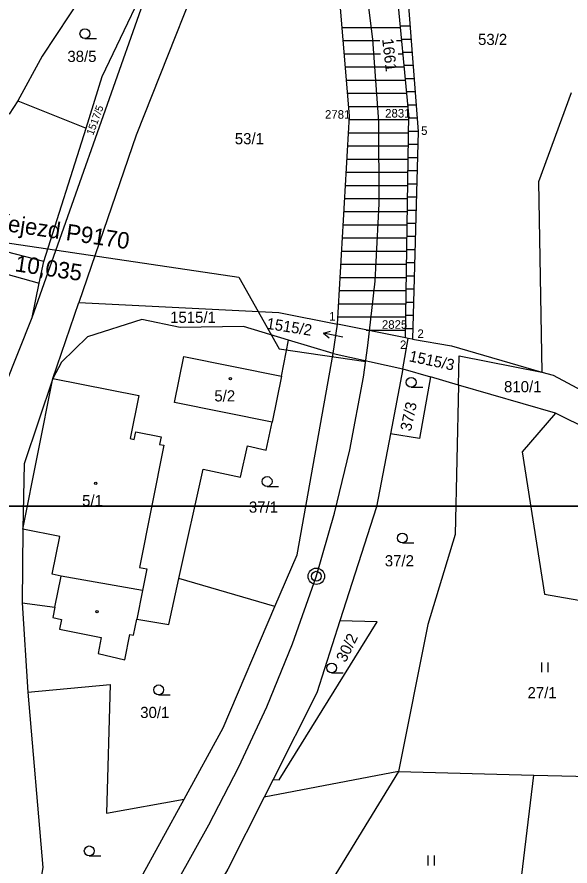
# Model space of a CAD drawing. Extents: x -553916 to -552953, y -1067469 to -1066637.
# Drawn here: x -553557.7 to -553473.7, y -1067154.7 to -1067025.6 of the extents above; entities that cross this region are included whole.
import ezdxf

# ---------------------------------------------------------------- set-up
doc = ezdxf.new("R2010")
doc.units = 0
for name, color, linetype in [('Hranice parcel', 7, 'Continuous'), ('Kolej', 7, 'Continuous'), ('Návěst místo trati', 7, 'Continuous'), ('Parcelní čísla', 7, 'Continuous'), ('Pop  PČ popisy', 7, 'Continuous'), ('Propustek', 7, 'Continuous'), ('Přejezd - štěrkové lože', 7, 'Continuous'), ('Vnitřní kresba', 7, 'Continuous'), ('Vrstva 1', 7, 'Continuous'), ('Vrstva 60', 7, 'Continuous'), ('Značky budov', 7, 'Continuous'), ('Značky kultur', 7, 'Continuous')]:
    doc.layers.add(name, color=color, linetype=linetype)

msp = doc.modelspace()

# ---------------------------------------------------------------- linework, layer by layer
at = {"layer": 'Hranice parcel'}
for p, q in [((-553555.44, -1067071.33), (-553535.85, -1067015.85)), ((-553473.53, -1067037.17), (-553478.45, -1067050.68)), ((-553473.53, -1067037.17), (-553478.45, -1067050.68)), ((-553557.59, -1067038.38), (-553547.23, -1067042.51)), ((-553553.65, -1067062.79), (-553547.23, -1067042.51)), ((-553478.45, -1067050.68), (-553477.96, -1067079.63)), ((-553478.45, -1067050.68), (-553477.96, -1067079.63)), ((-553553.65, -1067062.79), (-553569.79, -1067058.6)), ((-553570.64, -1067061.48), (-553554.35, -1067066.11)), ((-553554.35, -1067066.11), (-553553.65, -1067062.79)), ((-553555.44, -1067071.33), (-553554.35, -1067066.11)), ((-553552.27, -1067080.57), (-553548.33, -1067069.03)), ((-553559.6, -1067081.76), (-553555.44, -1067071.33)), ((-553517.54, -1067080.21), (-553516.45, -1067074.75)), ((-553509.66, -1067076.78), (-553516.45, -1067074.75)), ((-553490.63, -1067081.59), (-553490.53, -1067077.13)), ((-553490.63, -1067081.59), (-553490.53, -1067077.13)), ((-553490.53, -1067077.13), (-553477.96, -1067079.63)), ((-553490.53, -1067077.13), (-553477.96, -1067079.63)), ((-553517.54, -1067080.21), (-553518.94, -1067087.24)), ((-553490.63, -1067081.59), (-553494.87, -1067080.36)), ((-553475.9, -1067085.87), (-553490.63, -1067081.59)), ((-553461.02, -1067093.19), (-553475.9, -1067085.87)), ((-553518.53, -1067115.26), (-553533.13, -1067110.99)), ((-553556.94, -1067114.69), (-553556.09, -1067128.27)), ((-553499.73, -1067140.34), (-553520.16, -1067144.23)), ((-553499.73, -1067140.34), (-553516.39, -1067167.53)), ((-553499.73, -1067140.34), (-553516.39, -1067167.53)), ((-553499.73, -1067140.34), (-553479.18, -1067140.92)), ((-553482.63, -1067169.28), (-553479.18, -1067140.92)), ((-553479.18, -1067140.92), (-553459.64, -1067141.29))]:
    msp.add_line(p, q, dxfattribs=at)
for points in [[(-553515.43, -1066991.08), (-553526.38, -1067010.19), (-553539.65, -1067043.59), (-553548.33, -1067069.03)], [(-553547.23, -1067042.51), (-553544.77, -1067034.69), (-553535.85, -1067015.85)], [(-553547.68, -1067022.12), (-553553.91, -1067031.58), (-553557.59, -1067038.38)], [(-553557.59, -1067038.38), (-553558.91, -1067040.42), (-553564.16, -1067035.68)], [(-553548.33, -1067069.03), (-553517.95, -1067070.55), (-553509.03, -1067072.35)], [(-553516.45, -1067074.75), (-553523.31, -1067072.7), (-553532.92, -1067072.84), (-553538.78, -1067071.62), (-553547.04, -1067074.23), (-553550.96, -1067078.08), (-553552.27, -1067080.57)], [(-553497.61, -1067074.62), (-553491.7, -1067075.64), (-553477.96, -1067079.63)], [(-553518.94, -1067087.24), (-553533.8, -1067084.25), (-553532.39, -1067077.24), (-553517.54, -1067080.21)], [(-553477.96, -1067079.63), (-553476.25, -1067080.06), (-553464.58, -1067086.32)], [(-553552.27, -1067080.57), (-553556.64, -1067093.58), (-553556.86, -1067103.5), (-553556.94, -1067114.69)], [(-553490.63, -1067081.59), (-553491.15, -1067104.31), (-553495.3, -1067118.01), (-553499.73, -1067140.34)], [(-553490.63, -1067081.59), (-553491.15, -1067104.31), (-553495.3, -1067118.01), (-553499.73, -1067140.34)], [(-553475.9, -1067085.87), (-553480.97, -1067091.73), (-553477.55, -1067113.39), (-553465.08, -1067115.55)], [(-553533.13, -1067110.99), (-553529.45, -1067094.35), (-553523.77, -1067095.61), (-553522.71, -1067090.83), (-553519.87, -1067091.46), (-553518.94, -1067087.24)], [(-553540.05, -1067119.63), (-553539.55, -1067117.17), (-553534.67, -1067117.97), (-553533.13, -1067110.99)], [(-553556.94, -1067114.69), (-553551.99, -1067115.38), (-553552.31, -1067116.95)], [(-553552.31, -1067116.95), (-553550.99, -1067117.22), (-553551.28, -1067118.69), (-553544.93, -1067119.96), (-553545.42, -1067122.41), (-553541.36, -1067123.37), (-553540.59, -1067119.53), (-553540.05, -1067119.63)], [(-553518.82, -1067141.56), (-553517.91, -1067141.59), (-553503, -1067117.58), (-553508.67, -1067117.46)], [(-553556.09, -1067128.27), (-553543.56, -1067127.12), (-553544.12, -1067146.66), (-553532.35, -1067144.53)], [(-553556.09, -1067128.27), (-553553.82, -1067154.93), (-553557.64, -1067176.88)]]:
    msp.add_lwpolyline(points, dxfattribs=at)
at = {"layer": 'Kolej'}
for points in [[(-553503.32, -1067065.81), (-553502.68, -1067054.03), (-553502.76, -1067041.5), (-553503.63, -1067029.06), (-553504.76, -1067019.97), (-553506.18, -1067011.39), (-553508.33, -1067001.39), (-553510.95, -1066991.62), (-553512.92, -1066985.29), (-553515.65, -1066977.35), (-553517.42, -1066972.53), (-553519.16, -1066967.95), (-553522.89, -1066958.38), (-553529.1, -1066942.55), (-553538.69, -1066918.11), (-553542.91, -1066907.33), (-553546.69, -1066897.68), (-553555.03, -1066876.44), (-553564.64, -1066851.89), (-553574.24, -1066827.43), (-553583.19, -1066804.62)], [(-553543.17, -1067173.82), (-553538.26, -1067165.53), (-553533.28, -1067156.93), (-553528.57, -1067148.43), (-553524.02, -1067139.63), (-553519.75, -1067130.49), (-553515.84, -1067120.93), (-553512.27, -1067110.73), (-553509.46, -1067101.06), (-553507.13, -1067091.41), (-553505.08, -1067080.38), (-553504.39, -1067075.58), (-553503.32, -1067065.81)]]:
    msp.add_lwpolyline(points, dxfattribs=at)
at = {"layer": 'Návěst místo trati'}
for radius in [1.25, 0.752]:
    msp.add_circle((-553512.25, -1067110.66), radius, dxfattribs=at)
at = {"layer": 'Pop  PČ popisy'}
for p, q in [((-553511.16, -1067073.68), (-553510.07, -1067073.4)), ((-553508.22, -1067074.31), (-553511.16, -1067073.68)), ((-553511.16, -1067073.68), (-553510.28, -1067074.38))]:
    msp.add_line(p, q, dxfattribs=at)
at = {"layer": 'Propustek'}
for p, q in [((-553499.28, -1067010.65), (-553496.78, -1067043.02)), ((-553499.48, -1067026.97), (-553498.02, -1067026.97)), ((-553508.33, -1067027.22), (-553499.45, -1067027.22)), ((-553508.16, -1067029.22), (-553502.6, -1067029.22)), ((-553500.05, -1067029.22), (-553499.26, -1067029.22)), ((-553499.28, -1067028.97), (-553497.87, -1067028.97)), ((-553499.09, -1067030.97), (-553497.71, -1067030.97)), ((-553508, -1067031.22), (-553502.47, -1067031.22)), ((-553499.81, -1067031.22), (-553499.06, -1067031.22)), ((-553507.83, -1067033.22), (-553498.87, -1067033.22)), ((-553498.89, -1067032.97), (-553497.56, -1067032.97)), ((-553507.67, -1067035.22), (-553498.67, -1067035.22)), ((-553498.7, -1067034.97), (-553497.4, -1067034.97)), ((-553507.51, -1067037.22), (-553498.48, -1067037.22)), ((-553498.51, -1067036.97), (-553497.25, -1067036.97)), ((-553507.34, -1067039.22), (-553498.29, -1067039.22)), ((-553498.31, -1067038.97), (-553497.09, -1067038.97)), ((-553507.25, -1067041.22), (-553498.18, -1067041.22)), ((-553498.18, -1067040.97), (-553496.94, -1067040.97)), ((-553507.37, -1067043.22), (-553498.21, -1067043.22)), ((-553498.21, -1067042.97), (-553496.78, -1067042.97)), ((-553496.78, -1067043.02), (-553497.61, -1067074.62)), ((-553498.24, -1067044.97), (-553496.83, -1067044.97)), ((-553507.48, -1067045.22), (-553498.24, -1067045.22)), ((-553507.59, -1067047.22), (-553498.27, -1067047.22)), ((-553498.27, -1067046.97), (-553496.88, -1067046.97)), ((-553498.3, -1067048.97), (-553496.94, -1067048.97)), ((-553507.71, -1067049.22), (-553498.3, -1067049.22)), ((-553507.82, -1067051.22), (-553498.33, -1067051.22)), ((-553498.33, -1067050.97), (-553496.99, -1067050.97)), ((-553507.94, -1067053.22), (-553498.36, -1067053.22)), ((-553498.36, -1067052.97), (-553497.04, -1067052.97)), ((-553508.05, -1067055.22), (-553498.39, -1067055.22)), ((-553498.39, -1067054.97), (-553497.09, -1067054.97)), ((-553508.17, -1067057.22), (-553498.42, -1067057.22)), ((-553498.42, -1067056.97), (-553497.15, -1067056.97)), ((-553508.28, -1067059.22), (-553498.45, -1067059.22)), ((-553498.45, -1067058.97), (-553497.2, -1067058.97)), ((-553508.39, -1067061.22), (-553498.48, -1067061.22)), ((-553498.48, -1067060.97), (-553497.25, -1067060.97)), ((-553508.51, -1067063.22), (-553498.51, -1067063.22)), ((-553498.51, -1067062.97), (-553497.3, -1067062.97)), ((-553508.62, -1067065.22), (-553498.54, -1067065.22)), ((-553498.54, -1067064.97), (-553497.36, -1067064.97)), ((-553498.57, -1067066.97), (-553497.41, -1067066.97)), ((-553508.74, -1067067.22), (-553498.57, -1067067.22)), ((-553508.85, -1067069.22), (-553498.6, -1067069.22)), ((-553498.6, -1067068.97), (-553497.46, -1067068.97)), ((-553498.63, -1067070.97), (-553497.51, -1067070.97)), ((-553508.97, -1067071.22), (-553498.63, -1067071.22)), ((-553498.68, -1067074.42), (-553509.03, -1067072.35)), ((-553504.67, -1067073.22), (-553498.66, -1067073.22)), ((-553498.66, -1067072.97), (-553497.57, -1067072.97)), ((-553498.28, -1067074.5), (-553498.68, -1067074.42)), ((-553497.61, -1067074.62), (-553498.28, -1067074.5))]:
    msp.add_line(p, q, dxfattribs=at)
for points in [[(-553498.68, -1067074.42), (-553498.17, -1067040.43), (-553500.08, -1067020.73), (-553503.77, -1067001.28), (-553507.63, -1066988.97), (-553505.83, -1066988.51)], [(-553509.03, -1067072.35), (-553507.22, -1067040.68), (-553509.18, -1067016.9), (-553515.22, -1066991.69), (-553515.43, -1066991.08)]]:
    msp.add_lwpolyline(points, dxfattribs=at)
at = {"layer": 'Přejezd - štěrkové lože'}
msp.add_lwpolyline([(-553562.67, -1067059.43), (-553524.03, -1067065.17), (-553517.87, -1067076.06), (-553504.74, -1067077.98)], dxfattribs=at)
at = {"layer": 'Vnitřní kresba'}
for p, q in [((-553556.86, -1067103.5), (-553552.27, -1067080.57)), ((-553552.27, -1067080.57), (-553539.23, -1067083.19)), ((-553539.23, -1067083.19), (-553540.54, -1067089.73)), ((-553539.93, -1067089.85), (-553539.7, -1067088.69)), ((-553539.7, -1067088.69), (-553535.83, -1067089.46)), ((-553540.54, -1067089.73), (-553539.93, -1067089.85)), ((-553535.83, -1067089.46), (-553536.06, -1067090.62)), ((-553535.4, -1067090.75), (-553539.11, -1067109.32)), ((-553536.06, -1067090.62), (-553535.4, -1067090.75)), ((-553551.22, -1067104.63), (-553556.86, -1067103.5)), ((-553552.37, -1067110.36), (-553551.22, -1067104.63)), ((-553539.11, -1067109.32), (-553538.03, -1067109.53)), ((-553538.03, -1067109.53), (-553538.68, -1067112.82)), ((-553551.04, -1067110.63), (-553552.37, -1067110.36)), ((-553551.99, -1067115.38), (-553551.04, -1067110.63)), ((-553538.68, -1067112.82), (-553551.04, -1067110.63)), ((-553538.68, -1067112.82), (-553539.55, -1067117.17))]:
    msp.add_line(p, q, dxfattribs=at)
at = {"layer": 'Vrstva 1'}
for p, q in [((-553509.66, -1067076.78), (-553509.03, -1067072.35)), ((-553499.07, -1067079.14), (-553498.28, -1067074.5)), ((-553509.66, -1067076.78), (-553499.07, -1067079.14)), ((-553499.07, -1067079.14), (-553500.97, -1067088.98)), ((-553499.07, -1067079.14), (-553494.87, -1067080.36)), ((-553518.82, -1067141.56), (-553520.16, -1067144.23))]:
    msp.add_line(p, q, dxfattribs=at)
for points in [[(-553300, -1066816.27), (-553300, -1067100), (-553800, -1067100), (-553800, -1066816.27)], [(-553518.53, -1067115.26), (-553515.16, -1067107.38), (-553509.66, -1067076.78)], [(-553494.87, -1067080.36), (-553496.55, -1067089.69), (-553500.97, -1067088.98)], [(-553500.97, -1067088.98), (-553503.12, -1067100.12), (-553508.67, -1067117.46)], [(-553800, -1067410.27), (-553800, -1067100), (-553300, -1067100), (-553300, -1067410.27)], [(-553532.35, -1067144.53), (-553526.4, -1067133.68), (-553518.53, -1067115.26)], [(-553508.67, -1067117.46), (-553512.16, -1067128.37), (-553518.82, -1067141.56)], [(-553551.38, -1067177.98), (-553539.14, -1067156.92), (-553532.35, -1067144.53)], [(-553520.16, -1067144.23), (-553525.7, -1067155.19), (-553540.6, -1067180.86)]]:
    msp.add_lwpolyline(points, dxfattribs=at)
at = {"layer": 'Vrstva 60'}
for p, q in [((-553507.22, -1067040.68), (-553507.22, -1067040.68)), ((-553498.17, -1067040.43), (-553498.17, -1067040.43)), ((-553496.78, -1067043.02), (-553496.78, -1067043.02)), ((-553509.03, -1067072.35), (-553509.03, -1067072.35)), ((-553498.68, -1067074.42), (-553498.68, -1067074.42)), ((-553498.28, -1067074.5), (-553498.28, -1067074.5)), ((-553497.61, -1067074.62), (-553497.61, -1067074.62))]:
    msp.add_line(p, q, dxfattribs=at)
at = {"layer": 'Značky budov'}
for centre in [(-553525.3, -1067080.61), (-553545.78, -1067096.51), (-553545.57, -1067116.03)]:
    msp.add_circle(centre, 0.175, dxfattribs=at)
at = {"layer": 'Značky kultur'}
for p, q in [((-553547.42, -1067028.91), (-553545.67, -1067028.91)), ((-553497.83, -1067081.93), (-553496.08, -1067081.93)), ((-553519.72, -1067097), (-553517.97, -1067097)), ((-553499.17, -1067105.6), (-553497.42, -1067105.6)), ((-553477.99, -1067125.26), (-553477.99, -1067123.76)), ((-553476.99, -1067125.26), (-553476.99, -1067123.76)), ((-553509.92, -1067125.35), (-553508.17, -1067125.35)), ((-553536.21, -1067128.68), (-553534.46, -1067128.68)), ((-553546.76, -1067153.17), (-553545.01, -1067153.17)), ((-553495.26, -1067154.62), (-553495.26, -1067153.12)), ((-553494.26, -1067154.62), (-553494.26, -1067153.12))]:
    msp.add_line(p, q, dxfattribs=at)
for centre in [(-553547.42, -1067028.16), (-553497.83, -1067081.18), (-553519.72, -1067096.25), (-553499.17, -1067104.85), (-553509.92, -1067124.6), (-553536.21, -1067127.93), (-553546.76, -1067152.42)]:
    msp.add_circle(centre, 0.75, dxfattribs=at)

# ---------------------------------------------------------------- texts
at = {"layer": 'Parcelní čísla'}
for s, p in [('53/2', (-553487.66, -1067029.88)), ('38/5', (-553550.08, -1067032.46)), ('53/1', (-553524.63, -1067044.97)), ('1515/1', (-553534.47, -1067072.13)), ('810/1', (-553483.71, -1067082.68)), ('5/2', (-553527.74, -1067084.08)), ('5/1', (-553547.84, -1067100)), ('37/1', (-553522.49, -1067100.99)), ('37/2', (-553501.83, -1067109.15)), ('27/1', (-553480.14, -1067129.21)), ('30/1', (-553539.01, -1067132.21))]:
    msp.add_text(s, height=1.7, dxfattribs=at).set_placement(p)
for s, height, rotation, p in [('1517/5', 1.14, 70, (-553546.16, -1067043.69)), ('1515/3', 1.7, 348, (-553498.25, -1067077.96)), ('30/2', 1.7, 64, (-553507.8, -1067123.87))]:
    msp.add_text(s, height=height, rotation=rotation, dxfattribs=at).set_placement(p)
at = {"layer": 'Přejezd - štěrkové lože'}
for s, p in [('přejezd P9170', (-553562.17, -1067057.78)), ('km 10,035', (-553563.49, -1067063.48))]:
    msp.add_text(s, height=2.5, rotation=351.5622, dxfattribs=at).set_placement(p)
at = {"layer": 'Vrstva 1'}
for s, rotation, p in [('1661', 276.6165, (-553502.25, -1067028.98)), ('1515/2', 351, (-553519.91, -1067073.02)), ('37/3', 78, (-553497.86, -1067088.69))]:
    msp.add_text(s, height=1.7, rotation=rotation, dxfattribs=at).set_placement(p)
at = {"layer": 'Vrstva 60'}
for s, p in [('2781', (-553510.93, -1067041.09)), ('2831', (-553501.79, -1067040.91)), ('5', (-553496.32, -1067043.55)), ('1', (-553510.29, -1067071.78)), ('2825', (-553502.28, -1067073.03)), ('2', (-553496.88, -1067074.42)), ('2', (-553499.53, -1067076.11))]:
    msp.add_text(s, height=1.3, dxfattribs=at).set_placement(p)

doc.saveas('drawing.dxf')
